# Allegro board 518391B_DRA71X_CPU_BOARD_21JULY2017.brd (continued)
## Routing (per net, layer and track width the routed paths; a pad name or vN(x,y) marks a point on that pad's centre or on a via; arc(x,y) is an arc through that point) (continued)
VIO_3V3_SD: length 12.1
  TOP w0.254: C544.1 v2(149.35,128.27) ; U70.8 155.84,130.19 v2(155.57,129.92) ; C545.1 v2(149.35,130.81) ; C542.1 v2(149.35,133.35) ; U70.7 v2(155.58,130.69)
  TOP w0.305: C541.1 151,130.18 C540.1 149.73,130.43 v2(149.35,130.81)
  BOTTOM w0.254: U68.1 149.34,133.34 v2(149.35,133.35) ; U67.1 149.34,130.8 v2(149.35,130.81) ; U66.1 149.34,128.26 v2(149.35,128.27)
  BOTTOM w0.305: P10.4 149.79,130.37 v2(149.35,130.81)
VMEDIA_16V0: length 14.2
  TOP w0.305: TP62.1 146.3,13.39 ; TP62.1 145.62,12.7 ; TP62.1 146.3,12.01
  BOTTOM w0.305: 145.77,13.24 TP62.1 ; TP62.1 146.84,12.16 ; TP62.1 146.84,13.24 ; TP62.1 145.77,12.16 ; J17.8 125.54,22.12 ; J17.8 123.93,20.51 ; J17.8 125.54,20.51 ; J17.8 123.93,22.12 ; J17.7 123.54,22.12 ; J17.7 121.93,22.12 ; J17.7 121.93,20.51 ; J17.7 123.54,20.51
  vias: v3(143.51,12.19) v3(145.16,13.59)
VOSNS: length 6.2
  TOP w0.305: R47.2 C66.2 57.4,110.87 55.89,112.39 U19.12
VOUT3_INTB: length 76.4
  TOP w0.127: U30.31 140.34,71.37 v2(140.32,71.37) ; v1(95.24,91.53) U27.AC10
  LY3 w0.133: v2(137.41,95.5) 135.51,97.41 131.95,97.41 131.83,97.54 130.43,97.54 129.54,98.42 120.27,98.42 119.25,97.41 107.06,97.41 106.81,97.16 98.68,97.16 97.16,95.63 v2(96.01,95.63)
  LY4 w0.133: v2(137.41,95.5) 138.56,94.36 138.56,91.44 139.95,90.04 139.95,77.09 140.38,76.67 140.38,71.43 v2(140.32,71.37) ; v2(96.01,95.63) 95.24,94.86 v1(95.24,91.53)
  BOTTOM w0.127: R237.2 v2(96.01,95.63)
VOUT3B_CLK: length 41
  TOP w0.127: v2(142.76,61.71) 142.34,62.13 U30.10 ; R73.1 119.85,76.96 120.9,76.96 121.16,77.22 130.43,77.22 131.06,76.58 132.84,76.58 133.48,75.95 136.91,75.95 137.41,75.44 143.64,75.44 v2(144.02,75.06)
  LY4 w0.133: v2(144.02,75.06) 144.65,74.42 144.65,69.47 143.89,68.71 143.89,64.13 142.76,63.01 v2(142.76,61.71)
VOUT3B_D0: length 60.5
  TOP w0.127: 133.99,81.28 135.05,81.28 J8.2 ; U27.F1 101.86,80.16 105.8,76.21 116.19,76.21 116.59,75.82 121.16,75.82 121.67,76.33 127.63,76.33 127.89,76.58 129.16,76.58 129.54,76.2 131.95,76.2 132.08,76.33 132.72,76.33 133.35,75.69 136.4,75.69 v2(137.16,74.93) ; U30.43 136.39,66.05 v2(136.14,66.29)
  LY4 w0.133: v2(136.14,66.29) 136.65,66.8 136.65,72.39 137.16,72.9 v2(137.16,74.93) 137.16,75.44 136.83,75.77 J8.2
  BOTTOM w0.127: J8.2 135.25,79.5 135.22,79.46 R417.2
VOUT3B_D1: length 62.9
  TOP w0.102: U27.E2 100.44,79.18 101.52,79.18
  TOP w0.127: v2(136.53,74.55) 135.89,74.55 135.38,75.06 134.6,75.06 134.47,75.18 128.78,75.18 128.52,75.44 122.43,75.44 122.05,75.06 116.21,75.06 115.81,75.45 105.49,75.45 101.75,79.18 101.52,79.18 ; J8.4 135.76,82.55 133.99,82.55 ; U30.44 135.88,65.54 v2(135.64,65.79)
  LY4 w0.133: v2(135.64,65.79) 135.64,66.55 136.39,67.3 136.39,74.42 v2(136.53,74.55) 136.53,75.44 135.89,76.07 135.89,80.54 J8.4
  BOTTOM w0.127: J8.4 135.33,81.48 135.22,81.37 R418.2
VOUT3B_D2: length 64.2
  TOP w0.127: U27.E1 101.79,79.51 105.59,75.71 115.94,75.71 116.33,75.31 121.79,75.31 122.22,75.74 128.73,75.74 129.03,75.44 135.64,75.44 v2(135.89,75.18) ; U30.45 v2(136.14,65.04) ; 133.99,83.82 135.38,83.82 135.74,83.46 J8.6
  LY4 w0.133: J8.6 135.38,82.02 135.38,75.69 v2(135.89,75.18) 136.08,75 136.08,67.62 135.13,66.67 135.13,65.53 135.62,65.04 v2(136.14,65.04)
  BOTTOM w0.127: J8.6 135.28,83.46 135.22,83.4 R419.2
VOUT3B_D3: length 67.8
  TOP w0.127: J8.8 135.61,85.45 135.25,85.09 133.99,85.09 ; U27.C1 101.65,78.21 105.17,74.69 115.3,74.69 116.59,73.41 122.43,73.41 123.7,74.68 127.76,74.68 128.02,74.42 133.48,74.42 133.99,73.91 135.38,73.91 v2(135.64,74.17) ; U30.46 v2(135.41,64.54)
  LY4 w0.133: J8.8 134.87,83.49 134.87,75.44 135.64,74.68 v2(135.64,74.17) 135.82,73.99 135.82,68 134.87,67.05 134.87,65.09 v2(135.41,64.54)
  BOTTOM w0.127: R413.2 135.22,85.43 135.25,85.47 135.28,85.45 J8.8
VOUT3B_D4: length 69.4
  TOP w0.127: U27.D1 101.72,78.86 105.38,75.2 115.68,75.2 116.08,74.8 122.43,74.8 122.81,75.18 128.27,75.18 128.52,74.93 134.37,74.93 v2(134.87,74.42) ; J8.10 135.76,86.36 133.99,86.36 ; U30.47 v2(136.05,64.04)
  LY4 w0.133: v2(136.05,64.04) 135.31,64.04 134.61,64.75 134.61,67.18 135.56,68.13 135.56,73.49 134.87,74.17 v2(134.87,74.42) 134.49,74.8 134.49,85.09 J8.10
  BOTTOM w0.127: R420.2 135.22,87.46 135.25,87.5 135.33,87.43 J8.10
VOUT3B_D5: length 72.5
  TOP w0.102: U27.D2 100.44,78.53 101.52,78.53
  TOP w0.127: J8.12 135.05,87.63 133.99,87.63 ; U30.48 v2(135.43,63.55) ; 101.52,78.53 101.69,78.53 105.27,74.94 115.56,74.94 115.95,74.55 122.81,74.55 123.19,74.93 128.02,74.93 128.27,74.68 133.86,74.68 v2(134.11,74.42)
  LY4 w0.133: J8.12 134.11,86.69 v2(134.11,74.42) 135.3,73.24 135.3,68.49 134.24,67.44 134.24,64.26 134.96,63.55 v2(135.43,63.55)
  BOTTOM w0.127: R421.2 135.22,89.37 135.25,89.41 J8.12
VOUT3B_D6: length 54.6
  TOP w0.127: v2(111.25,58.42) 111.25,68.45 107.06,72.64 106.17,72.64 105.16,73.66 105.16,73.98 101.58,77.56 U27.B1 ; U30.1 137.84,62.02 137.16,61.34 136.65,61.34 v2(135.51,60.2)
  LY3 w0.133: v2(111.25,58.42) 111.74,57.93 133.24,57.93 v2(135.51,60.2)
  BOTTOM w0.127: v2(135.51,60.2) 135.51,61.09
VOUT3B_D7: length 59.1
  TOP w0.102: U27.B2 100.24,77.56 100.56,77.24 101.52,77.24
  TOP w0.127: v2(110.36,58.42) 110.36,62.61 109.47,63.5 109.47,69.6 106.68,72.39 105.79,72.39 104.78,73.41 104.78,73.99 101.52,77.24 ; U30.2 v2(138.34,61.82)
  LY3 w0.133: v2(110.36,58.42) 110.87,58.93 111.63,58.93 112.37,58.19 131.6,58.19 134.24,60.83 137.35,60.83 v2(138.34,61.82)
  BOTTOM w0.127: v2(138.34,61.82) 137.17,62.99 136.14,62.99 135.51,62.36
VOUT3B_D8: length 44.6
  TOP w0.102: U27.C2 100.44,77.88 101.52,77.88
  TOP w0.127: v2(138.18,72.01) 138.34,71.85 U30.35 ; 101.52,77.88 101.62,77.88 105.23,74.27 v2(105.77,74.27)
  LY3 w0.133: v2(105.77,74.27) 106.17,74.68 115.95,74.68 116.84,73.79 124.71,73.79 125.46,73.04 130.31,73.04 130.61,73.33 133.37,73.33 133.77,73.74 134.79,73.74 135.76,72.77 137.41,72.77 v2(138.18,72.01)
  BOTTOM w0.127: RJ17.2 v2(138.18,72.01)
VOUT3B_D9: length 47.2
  TOP w0.127: U30.36 137.84,71.2 137.67,71.37 137.67,74.3 v2(138.18,74.8) ; U27.D3 v1(99.79,79.18)
  LY3 w0.133: v2(138.18,74.8) 137.54,75.44 136.78,75.44 136.52,75.69 134.62,75.69 133.99,75.06 127.76,75.06 127.04,75.78 117.64,75.78 117.14,76.28 105.58,76.28 103.38,78.49 100.49,78.49 v1(99.79,79.18)
  BOTTOM w0.127: RJ16.2 v2(138.18,74.8)
VOUT3B_D10: length 47
  TOP w0.127: U27.A2 100.11,76.11 104.09,72.14 v2(105.16,72.14) ; U30.37 134.41,69.04 v2(133.73,69.72) 134.87,70.87 v2(134.87,73.02)
  LY3 w0.133: v2(105.16,72.14) 105.54,72.52 112.65,72.52 113.54,71.63 115.32,71.63 116.71,73.02 124.47,73.02 125.09,72.39 131.32,72.39 131.74,72.81 134.66,72.81 v2(134.87,73.02)
  BOTTOM w0.127: v2(133.73,69.72) 133.73,69.47 RJ20.2
VOUT3B_D11: length 46
  TOP w0.102: 99.79,76.17 99.79,77.04 99.46,77.37 U27.B3
  TOP w0.127: 99.79,76.17 99.79,76.08 104.24,71.63 v2(105.79,71.63) ; U30.38 133.82,68.54 v2(133.73,68.45)
  LY3 w0.133: v2(105.79,71.63) 106.3,72.14 112.27,72.14 113.04,71.37 115.56,71.37 116.95,72.76 124.22,72.76 125.35,71.63 v2(131.57,71.63)
  BOTTOM w0.127: v2(131.57,71.63) 131.57,68.83 131.95,68.45 132.72,68.45 RJ21.2 133.73,68.2 v2(133.73,68.45)
VOUT3B_D12: length 48.7
  TOP w0.102: 100.81,76.17 100.44,76.55 100.44,77.04 100.25,77.23 99.96,77.23 99.79,77.4 99.79,77.88 U27.C3
  TOP w0.127: v2(104.66,72.78) 101.52,75.92 101.07,75.92 100.81,76.17 ; U30.39 134.59,68.04 134.49,67.94 133.48,67.94 133.22,68.2 133.22,70.48 v2(133.73,70.99) 133.77,71.03 133.77,72.98 v2(134.09,73.3)
  LY3 w0.133: v2(134.09,73.3) 133.86,73.07 130.86,73.07 130.56,72.78 125.22,72.78 124.59,73.41 116.08,73.41 115.32,72.64 113.28,72.64 112.9,73.02 104.9,73.02 v2(104.66,72.78)
  BOTTOM w0.127: v2(133.73,70.99) 133.73,70.74 RJ19.2
VOUT3B_D13: length 48.1
  TOP w0.127: U30.40 134.09,67.54 v2(133.73,67.18) ; U27.C4 v1(99.14,77.88)
  LY3 w0.133: v2(132.97,73.79) 130.56,73.79 130.07,73.3 125.71,73.3 124.85,74.16 117.1,74.16 116.2,75.06 104.14,75.06 102.23,76.96 100.06,76.96 v1(99.14,77.88)
  LY4 w0.133: v2(132.97,73.79) 133.77,72.98 133.77,71.97 134.37,71.37 134.37,68.2 133.73,67.56 v2(133.73,67.18)
  BOTTOM w0.127: v2(133.73,67.18) 133.73,66.93 RJ22.2
VOUT3B_D14: length 49.8
  TOP w0.127: U30.41 134.35,67.04 133.99,66.67 133.35,66.67 132.84,67.18 132.84,71.88 v2(133.35,72.39) ; U27.A3 99.46,76.04 104.39,71.12 106.3,71.12 v2(106.68,71.5)
  LY3 w0.133: v2(106.68,71.5) 106.93,71.75 111.63,71.75 112.28,71.11 115.8,71.11 117.19,72.5 123.97,72.5 125.35,71.12 132.08,71.12 v2(133.35,72.39)
  BOTTOM w0.127: v2(133.35,72.39) RJ18.2
VOUT3B_D15: length 48.6
  TOP w0.102: 99.14,76.17 99.14,77.23 U27.B4
  TOP w0.127: 99.14,76.17 99.14,76.01 107.19,67.96 v2(107.19,65.41) ; v2(133.73,65.91) 134.61,66.79 136.28,66.79 136.53,66.54 U30.42
  LY3 w0.133: v2(133.73,65.91) 132.08,64.26 128.66,64.26 128.38,63.99 123.22,63.99 122.95,64.26 121.79,64.26 121.41,63.88 119.63,63.88 119.51,63.75 114.68,63.75 113.16,65.28 107.31,65.28 v2(107.19,65.41)
  BOTTOM w0.127: v2(133.73,65.91) 133.73,65.66 RJ23.2
VOUT3B_D16: length 53.1
  TOP w0.127: U30.25 v2(143.34,71.37) ; v2(143.12,76.15) 143.13,76.16 143.13,77.09 142.24,77.98 135.76,77.98 133.6,80.14 118.36,80.14 117.98,79.76 114.43,79.76 113.28,80.9 105.48,80.9 102.32,84.06 U27.M1
  LY4 w0.133: v2(143.12,76.15) 143.51,75.76 143.51,73.41 143.34,73.23 v2(143.34,71.37)
VOUT3B_D17: length 53.2
  TOP w0.102: 101.52,83.72 101.51,83.73 100.44,83.73 U27.M2
  TOP w0.127: U30.26 v2(142.84,70.76) ; v2(142.62,76.83) 141.73,77.72 134.37,77.72 132.21,79.88 118.62,79.88 118.24,79.5 114.17,79.5 113.03,80.64 105.36,80.64 102.29,83.72 101.52,83.72
  LY4 w0.133: v2(142.62,76.83) 142.62,75.82 143.13,75.31 143.13,73.53 142.88,73.28 142.88,70.8 v2(142.84,70.76)
VOUT3B_D18: length 52.1
  TOP w0.102: 101.52,83.09 100.44,83.09 U27.L2
  TOP w0.127: v2(142.15,76.07) 141.73,76.07 140.59,77.22 134.11,77.22 131.95,79.38 119.13,79.38 118.66,78.91 113.22,78.91 112.89,78.57 106.69,78.57 102.18,83.09 101.52,83.09 ; U30.27 v2(142.34,71.37)
  LY4 w0.133: v2(142.15,76.07) 142.15,73.36 142.37,73.15 142.37,71.4 v2(142.34,71.37)
VOUT3B_D19: length 51.1
  TOP w0.127: v2(141.73,76.83) 141.1,77.47 134.24,77.47 132.08,79.63 118.87,79.63 118.49,79.25 113.54,79.25 113.16,79.63 106.02,79.63 102.24,83.41 U27.L1 ; U30.28 v2(141.84,70.76)
  LY4 w0.133: v2(141.73,76.83) 141.73,73.02 141.86,72.9 141.86,70.78 v2(141.84,70.76)
VOUT3B_D20: length 52.5
  TOP w0.127: U30.29 v2(141.34,71.37) ; U27.K3 v1(99.79,82.43)
  LY3 w0.133: v1(99.79,82.43) 100.45,82.43 102.11,80.77 104.65,80.77 106.93,78.49 112.65,78.49 113.54,79.38 118.36,79.38 119.37,78.37 120.77,78.37 122.42,76.71 127.37,76.71 128.14,75.95 131.45,75.95 131.83,76.33 136.52,76.33 137.03,76.83 137.92,76.83 138.43,76.33 138.98,76.33 139.23,76.58 140.46,76.58 v2(140.97,76.07)
  LY4 w0.133: v2(141.34,71.37) 141.34,72.38 141.47,72.51 141.47,75.57 v2(140.97,76.07)
VOUT3B_D21: length 49.6
  TOP w0.102: 101.52,82.43 100.44,82.43 U27.K2
  TOP w0.127: U30.32 v2(139.84,70.76) ; v2(139.95,76.07) 139.66,76.37 138.37,76.37 138.03,76.71 133.86,76.71 131.7,78.87 119.63,78.87 119.16,78.4 113.58,78.4 113.25,78.07 106.48,78.07 102.12,82.43 101.52,82.43
  LY4 w0.133: v2(139.95,76.07) 139.95,75.55 139.96,75.55 139.96,72.14 139.83,72.01 139.83,70.78 v2(139.84,70.76)
VOUT3B_D22: length 48.1
  TOP w0.127: v2(139.19,75.95) 138.43,75.95 137.92,76.45 133.73,76.45 131.57,78.61 119.89,78.61 119.42,78.14 113.68,78.14 113.35,77.81 106.38,77.81 102.08,82.11 U27.J1 ; U30.33 v2(139.34,71.35)
  LY4 w0.133: v2(139.34,71.35) 139.32,71.37 139.32,72.14 139.7,72.52 139.7,75.44 v2(139.19,75.95)
VOUT3B_D23: length 48.1
  TOP w0.127: U30.34 v2(138.84,70.84) ; U27.K1 102.15,82.76 106.59,78.32 112.99,78.32 113.32,78.65 118.91,78.65 119.38,79.12 131.83,79.12 133.99,76.96 138.51,76.96 v2(138.68,76.78)
  LY4 w0.133: v2(138.68,76.78) 138.68,72.9 138.84,72.74 v2(138.84,70.84)
VOUT3B_DE: length 58.4
  TOP w0.102: 101.52,81.79 100.44,81.79 U27.J2
  TOP w0.127: U30.5 v2(139.84,61.21) ; v2(137.67,75.86) 137.33,76.2 133.6,76.2 132.25,77.56 131.1,77.56 130.3,78.36 120.14,78.36 119.51,77.72 118.36,77.72 117.94,77.3 117.39,77.3 116.8,77.89 113.79,77.89 113.46,77.56 106.27,77.56 102.04,81.79 101.52,81.79
  LY4 w0.133: v2(137.67,75.86) 137.67,64.39 139.84,62.22 v2(139.84,61.21)
VOUT3B_HSYNC: length 58
  TOP w0.127: U27.K4 v1(99.14,82.43) ; U30.3 v2(138.84,61.21)
  LY4 w0.133: v2(138.84,61.21) 136.02,61.21 132.97,64.26 132.97,70.99 131.52,72.44 v2(131.52,77.98) ; v2(114.55,80.64) 112.39,80.64 111.89,81.15 102.18,81.15 101.67,81.66 101.64,81.66 100.49,82.82 99.52,82.82 v1(99.14,82.43)
  BOTTOM w0.127: v2(131.52,77.98) 130.81,77.98 129.79,78.99 116.2,78.99 v2(114.55,80.64)
VOUT3B_VSYNC: length 55.3
  TOP w0.127: v2(131.95,77.01) 131.14,77.01 130.05,78.1 120.4,78.1 119.63,77.34 118.36,77.34 118.07,77.05 117.13,77.05 116.55,77.64 113.89,77.64 113.56,77.3 106.17,77.3 105.49,77.98 102.01,81.46 U27.H1 ; U30.4 v2(139.34,61.82)
  LY4 w0.133: v2(131.95,77.01) 131.95,73.66 132.84,72.77 132.84,71.88 133.31,71.42 133.31,64.56 135,62.86 138.3,62.86 v2(139.34,61.82)
VPOC_DISPLAY: length 3
  LY4 w0.635: 159.27,69 P2.2 158.21,67.93
  BOTTOM w0.305: C454.1 v2(164.21,59.56)
  vias: v2(162.31,60.5) v2(163.32,60.5)
VREF_DBG: length 21.4
  TOP w0.203: J14.12 119.68,46.61 120.19,46.1 121.41,46.1 121.92,45.59 123.99,45.59 126.15,47.75 126.15,48.81 126.62,49.28 126.62,51.31 127,51.69 R308.2
  TOP w0.305: R308.2 125.09,54.1 124.71,54.48 123.06,54.48 122.75,54.17 J14.1
VSW_3V3: length 2.7
  TOP w0.305: 66.37,44.96 TP42.1 ; TP42.1 67.06,45.64 ; TP42.1 67.06,44.27 ; TP42.1 67.74,44.96
VSW_5V0: length 292.7
  TOP w0.203: U17.10 114.6,152.83 v2(114.3,152.53)
  TOP w0.279: U32.8 84.47,60.67 v2(84.48,60.68)
  TOP w0.305: R186.2 v2(66.93,16.89) ; R185.2 v2(69.34,16.89) ; TP57.1 95.17,24.64 ; TP57.1 93.8,24.64 ; TP57.1 94.49,25.32 ; TP57.1 94.49,23.95 ; R31.1 R30.2 ; R30.2 v2(110.74,153.54) ; R30.2 R28.2 ; v2(68.58,11.43) 68.33,11.68 R167.1 R166.1
  LY3 w0.305: v2(116.59,118.75) 116.59,111 121.79,105.79 131.57,105.79 136.4,100.97 141.6,100.97 142.24,100.33 150.24,100.33 v2(150.75,99.82) ; v2(94.49,25.78) 106.93,25.78 111.12,29.97 122.17,29.97 123.57,31.37 135.51,31.37 138.94,34.8 138.94,45.08 140.12,46.27 151.47,46.27 151.89,45.85 156.59,45.85 159,48.26 159,54.99 158.24,55.75 158.24,60.45 153.54,65.15 v2(153.54,71.25)
  LY3 w0.508: v2(68.96,47.37) 68.96,45.97 71.25,43.69 71.25,40.13 74.55,36.83 74.55,34.54 75.31,33.78 75.31,32.26 75.82,31.75 v2(75.82,28.32) ; v2(75.44,62.36) 76.2,63.12 82.04,63.12 v2(84.48,60.68)
  LY4 w0.305: 94.49,23.95 TP57.1 ; TP57.1 94.49,25.32 ; TP57.1 95.17,24.64 ; TP57.1 93.8,24.64 ; v2(116.08,148.59) 116.59,148.08 v2(116.59,118.75) ; v2(153.54,71.25) 153.54,81.91 150.75,84.71 150.75,95.38 150.11,96.01 150.11,97.41 150.75,98.04 v2(150.75,99.82)
  BOTTOM w0.203: v2(114.3,152.53) C269.1
  BOTTOM w0.305: v2(116.08,148.59) 114.3,150.37 v2(114.3,152.53) 113.79,152.53 113.41,152.15 112.14,152.15 v2(110.74,153.54) ; C527.1 v2(75.82,28.32) ; v2(84.48,60.68) C441.1
  BOTTOM w0.508: v2(75.44,62.36) 75.44,63.63 74.93,64.13 74.04,64.13 72.26,62.36 71.25,62.36 68.6,59.71 68.6,47.73 v2(68.96,47.37)
  vias: v2(76.96,29.34) v2(93.34,25.78)
VSYS_3V3: length 175.5
  TOP w0.254: 85.97,60.44 v2(85.67,60.73) ; v2(87.35,60.86) 86.97,60.47 U32.3 ; U32.22 80.8,54.38 v2(80.77,54.36) ; v2(83.46,60.73) 83.47,60.73 U32.10
  TOP w0.279: v2(80.48,56.48) 80.68,56.48 80.75,56.41 81.15,56.41 81.21,56.39 81.23,56.38 U32.18 ; U32.5 85.97,60.44 ; v2(90.04,55.77) 89.92,55.89 U32.42 ; U32.37 v2(89.92,53.39) ; U32.46 v2(89.63,57.88)
  TOP w0.305: U24.16 v2(121.78,97.65) ; U42.4 v2(88.7,33.2) ; R22.2 v2(78.74,129.35) ; R23.2 v2(72.26,129.48) ; v2(70.87,16.89) R188.2 R187.2 ; 124.84,29.97 124.21,29.97 v2(123.82,30.35) ; v2(136.91,53.21) 137.23,52.88 U37.34 ; v2(86.36,50.55) 86.36,51.18 85.97,51.57 U32.32 ; U37.60 127.11,44.35 v2(126.85,44.09) ; U45.5 131.83,29.97 v2(131.44,30.35) ; U38.8 v2(108.2,44.7) ; Q8.4 88.38,39.86 v2(88.39,39.88) ; U37.23 v2(141.08,45.35) ; v2(84.2,50.8) 84.47,51.07 U32.29 ; U37.8 v2(133.74,38.99) ; R41.2 v2(70.48,112.52) ; v2(110.11,36.45) C190.1
  TOP w0.508: v2(142.62,41.66) 143.05,41.66 C181.1 143.05,40.64 v2(142.62,40.64) ; 130.75,31.62 124.33,31.62 123.82,31.11 v2(123.82,30.35) ; 130.75,31.62 131.44,30.93 v2(131.44,30.35) ; 130.75,31.62 130.81,31.68 v2(130.81,38.35)
  LY3 w0.305: v2(70.87,16.89) 71.5,17.53 71.5,25.65 70.36,26.8 70.36,33.65 68.71,35.31 68.71,37.21 v2(67.06,38.86)
  LY3 w0.508: v2(79.26,152) 79.26,149.08 v2(80.39,147.95) 80.39,146.65 v2(79.39,145.65) 79.39,144.64 80.9,143.13 80.9,141.99 v2(80.52,141.6) ; v2(101.73,117.35) 101.22,117.35 100.84,116.97 100.84,116.08 101.47,115.44 101.47,115.06 103.12,113.41 111.89,113.41 120.78,104.52 v2(121.79,104.52)
  LY4 w0.508: v2(78.74,129.35) 78.74,130.81 77.98,131.57 77.98,133.1 80.96,136.08 80.96,141.16 v2(80.52,141.6) ; v2(121.78,97.65) 121.79,97.66 v2(121.79,104.52)
  BOTTOM w0.254: v2(84.2,50.8) 84.44,51.04 C475.1 ; C464.1 81.24,55.72 v2(80.48,56.48) ; C447.1 83.24,60.95 v2(83.46,60.73) ; R347.2 106.3,43.69 106.93,44.32 106.99,44.32 107.31,44.65 C497.1 ; v2(80.77,54.36) 80.39,54.36 C470.1 ; R354.1 138.18,41.53 v2(138.05,41.66) ; R319.1 v2(140.46,51.18)
  BOTTOM w0.305: R347.2 R350.1 R351.1 v2(106.3,40) ; C500.2 126.87,44.07 v2(126.85,44.09) ; 88.27,61.47 87.96,61.47 v2(87.35,60.86) ; R345.2 v2(135.89,45.78) ; v2(138.43,43.52) 138.47,43.52 138.68,43.31 R348.1 ; C554.2 78.49,109.63 v2(78.25,109.87) U76.4 ; v2(75.83,126.77) 75.82,126.76 75.82,126.75 75.56,126.49 R217.2 ; v2(121.78,97.65) 121.78,96.91 C290.1 ; R370.2 88.27,40 v2(88.39,39.88) ; C505.2 133.73,39 v2(133.74,38.99) ; R414.2 v2(80.39,147.95) 80.9,148.46 R416.1 ; v2(90.04,55.77) 90.72,55.09 C469.1 ; R376.2 110.11,35.31 v2(110.11,36.45) ; v2(86.36,50.55) 86.36,51.31 86.07,51.6 C474.1 ; C478.2 v2(136.91,53.21) ; C450.1 90.54,58.79 v2(89.63,57.88) ; C548.1 79.12,152.15 v2(79.26,152) U71.5 ; U72.5 v2(79.39,145.65) ; C522.1 v2(123.82,30.35) ; v2(108.2,44.7) C497.1 ; U74.6 v2(28.19,139.06) C549.2 ; R415.2 v2(80.52,141.6) ; C521.1 v2(131.44,30.35)
  BOTTOM w0.508: R374.1 v2(113.54,33.08)
  vias: v2(67.06,40.89) v2(67.06,39.75) v2(68.58,40.39) v2(91.69,37.46) v2(91.69,36.7) v2(93.98,112.9) v2(95,112.9) v2(96.01,112.9) v2(97.03,112.9) v2(98.04,112.9) v2(100.33,118.87) v2(101.09,118.87) v2(102.23,118.87)
VSYS_5V0: length 214.5
  TOP w0.203: U18.16 79.13,127.63 78.87,127.89 v2(78.87,128.4)
  TOP w0.254: U70.4 v2(158.32,132.38) ; U20.4 102.41,115.75 v2(102.23,115.57) ; U48.4 91.36,28.52 v2(91.19,28.7)
  TOP w0.305: 83.64,32.51 TP51.1 ; TP51.1 84.33,33.2 ; TP51.1 85.01,32.51 ; TP51.1 84.33,31.83 ; R143.2 v2(94.11,32)
  TOP w0.508: U46.3 v2(126.11,37.02) ; U45.3 v2(133.73,37.02)
  LY3 w0.305: v2(102.23,115.57) 103.5,114.3 112.27,114.3 121.41,105.16 131.19,105.16 v2(132.21,104.14) 136.02,100.33 v2(141.35,100.33)
  LY4 w0.305: 84.33,31.83 TP51.1 ; TP51.1 84.33,33.2 ; TP51.1 85.01,32.51 ; TP51.1 83.64,32.51 ; v2(102.23,115.57) 102.49,115.82 102.49,117.6 101.98,118.11 99.95,118.11 99.82,118.24 90.68,118.24 84.2,124.71 82.42,124.71 80.26,126.87 79.38,126.87 78.87,127.38 v2(78.87,128.4) ; v2(141.35,100.33) 141.35,93.98 142.24,93.09 142.24,90.3 143.51,89.03 143.51,81.79 145.29,80.01 145.29,76.71 146.69,75.31 146.69,69.85 146.18,69.34 146.18,68.45 146.56,68.07 146.56,61.72 144.78,59.94 144.78,56.77 v2(144.02,56.01)
  LY4 w0.508: v2(158.32,132.38) 146.86,132.38 146.05,131.57 142.37,131.57 132.21,121.41 v2(132.21,104.14)
  BOTTOM w0.305: v2(133.73,37.02) 133.73,37.97 134.62,38.86 134.62,52.96 137.67,56.01 v2(144.02,56.01)
  BOTTOM w0.508: v2(126.11,37.02) 126.11,35.81 ; v2(133.73,37.02) 133.73,35.81
  vias: v2(92.96,29.21) v2(94.49,30.61) v2(94.49,29.84) v2(94.49,28.7)
VSYS_10V5: length 19.7
  TOP w0.305: 151.26,25.6 TP55.1 ; TP55.1 151.94,26.29 ; TP55.1 150.57,26.29 ; TP55.1 151.26,26.98 ; U19.24 v2(51.33,121.39) ; R172.2 150.24,23.49 151.69,24.94 L54.2
  LY4 w0.305: TP55.1 151.26,26.98 ; TP55.1 151.26,25.6 ; TP55.1 151.94,26.29 ; TP55.1 150.57,26.29
  vias: v2(151.26,28.07)
VSYS_16V0: length 40.3
  TOP w0.305: 70.48,129.54 71.37,128.65 71.37,114.55 66.8,109.98 R46.2 60.83,109.98 60.71,110.11 R47.1 ; 65.1,134.24 TP7.1 ; TP7.1 65.79,133.55 ; TP7.1 65.79,134.93 ; TP7.1 66.47,134.24 ; R182.1 v2(161.8,11.68)
  LY5_PWR w0.305: TP7.1 66.47,134.24 ; TP7.1 65.79,134.93 ; TP7.1 65.79,133.55 ; TP7.1 65.1,134.24 ; J13.1 162.69,54.66 ; J13.1 163.75,53.59 ; J13.1 161.62,53.59 ; J13.1 162.69,52.53
  BOTTOM w0.305: C266.2 v2(59.82,132.33)
  vias: v2(60.71,132.33) v2(61.59,132.33) v2(62.48,132.33) v2(63.75,132.33) v2(64.64,132.33) v2(65.53,132.33) v2(66.42,132.33) v2(67.69,132.33) v2(68.58,132.33) v2(69.47,132.33) v2(70.36,132.33) v2(92.33,152.4) v2(94.36,151.13) v2(94.36,150.11) v2(94.36,149.1) v2(142.37,31.62) v2(142.37,30.61) v2(143,29.97) v2(143.38,21.08) v2(144.02,29.97) v2(144.4,21.08) v2(145.16,20.45) v2(145.16,19.43) v2(161.93,18.03) v2(163.07,18.03) v2(164.08,18.03) v2(165.1,18.03)
VTT_DDR:
  vias: v2(48.51,69.98) v2(50.67,69.98) v2(53.47,69.98) v2(56.13,69.98) v2(58.8,69.98) v2(61.59,69.85) v2(61.72,58.93) v2(61.72,57.91) v2(61.72,56.77) v2(61.72,55.75) v2(61.72,54.61) v2(61.72,53.59) v2(62.71,52.32) v2(63.12,69.85) v2(64.26,69.85)
VTUN_1V8: length 18.5
  TOP w0.305: v2(52.7,56.13) C150.1 C149.1 51.69,55.5 50.77,54.58 U34.25 ; TP52.1 64.01,32.94 ; TP52.1 64.69,32.26 ; TP52.1 64.01,31.57 ; TP52.1 63.32,32.26 ; U36.45 32.07,56.07 32.51,56.52 32.89,56.52 33.78,57.4 C138.1 C139.1 v2(34.8,57.47)
  LY3 w0.305: 64.01,31.57 TP52.1 ; TP52.1 64.69,32.26 ; TP52.1 64.01,32.94 ; TP52.1 63.32,32.26
  BOTTOM w0.305: C460.1 52.45,56.39 v2(52.7,56.13) ; v2(34.8,57.47) 34.8,57.78 C452.1
  vias: v2(63.12,33.02)
VTUN_3V3: length 16.1
  TOP w0.254: v2(52.83,46.1) C170.2 C169.2 50.37,46.78 U34.12 ; v2(34.04,41.91) C180.2 C179.2 31.57,42.6 U36.18
  TOP w0.305: TP56.1 64.01,25.45 ; TP56.1 63.32,24.76 ; TP56.1 64.01,24.08 ; TP56.1 64.69,24.76
  TOP w0.508: R162.2 v2(37.85,23.49) ; R153.2 v2(56.52,27.56)
  LY3 w0.305: 64.01,24.08 TP56.1 ; TP56.1 63.32,24.76 ; TP56.1 64.01,25.45 ; TP56.1 64.69,24.76
  BOTTOM w0.254: C501.2 v2(34.04,41.91) ; v2(52.83,46.1) C494.2
  vias: v2(63.12,25.53)
VUSB_5V0: length 23.1
  TOP w0.305: U12.15 v2(156.53,146.81) ; 83.95,149.81 TP2.1 83.26,150.5 ; R7.1 v2(127.25,144.14) ; U12.14 155.89,146.62 v2(155.7,146.81)
  TOP w0.508: v2(159.64,145.54) 159.64,146.05 C12.1 158.62,146.05 v2(158.62,145.54)
  LY3 w0.305: 83.95,149.81 TP2.1 ; TP2.1 83.95,151.18 ; TP2.1 83.26,150.5 ; TP2.1 84.63,150.5
  BOTTOM w0.305: v2(87.5,143.13) 88.99,141.64 90.12,141.64 90.42,141.34 90.42,140.46 91.19,139.7 R210.2 ; R198.1 v2(153.54,149.48) ; C263.1 155.57,146.69 v2(155.7,146.81) ; 92.33,147.83 93.09,148.59 v2(95.76,148.59) ; C262.2 v2(96.52,146.81)
  vias: v2(82.8,148.97) v2(82.8,147.83) v2(82.8,146.81) v2(82.8,145.67) v2(124.33,144.78) v2(124.59,143.51) v2(124.59,142.49)
W_MMC1_CLK: length 12
  TOP w0.127: U21.46 149.84,102.59 v2(149.48,102.23)
  LY4 w0.133: v2(150.06,110.62) 149.73,110.29 149.73,108.84 150.11,108.46 150.11,105.92 149.48,105.28 v2(149.48,102.23)
  BOTTOM w0.127: RU1.13 v2(150.06,110.62)
W_MMC1_CMD: length 15.1
  TOP w0.127: v2(147.7,102.23) 147.7,102.26 147.84,102.4 U21.44
  LY4 w0.133: v2(147.7,102.23) 147.7,104.27 147.57,104.39 147.57,107.7 148.21,108.33 148.21,111.25 148.08,111.38 148.08,114 v2(148.11,114.02)
  BOTTOM w0.127: RU1.10 v2(148.11,114.02)
W_MMC1_D0: length 6.2
  TOP w0.127: v2(146.69,102.36) 146.84,102.51 U21.43
  BOTTOM w0.127: RU2.3 144.1,104.94 v2(146.69,102.36)
W_MMC1_D1: length 8.5
  TOP w0.127: U21.41 144.84,102.29 144.02,101.47 143.13,101.47 v2(142.49,102.11)
  BOTTOM w0.127: RU2.6 142.15,102.45 v2(142.49,102.11)
W_MMC1_D2: length 10.6
  TOP w0.127: v2(144.14,102.36) 143.84,102.67 U21.40
  LY3 w0.133: v2(144.14,102.36) 146.43,104.65 146.81,104.65 147.7,105.54 150.24,105.54 v2(150.71,105.07)
  BOTTOM w0.127: RU1.3 v2(150.71,105.07)
W_MMC1_D3: length 6.7
  TOP w0.127: U21.42 145.84,102.4 v2(145.8,102.36)
  LY3 w0.133: v2(148.76,104.69) 147.83,103.76 147.19,103.76 v2(145.8,102.36)
  BOTTOM w0.127: RU1.6 v2(148.76,104.69)
WL_EN: length 83.3
  TOP w0.127: U21.9 v2(149.84,121.39) ; v2(133.99,93.22) 131.7,93.22 130.18,91.69 127.13,91.69 126.62,91.19 121.03,91.19 119.55,89.7 114.52,89.7 112.65,91.57 105.54,91.57 104.53,90.56 U27.AB1
  LY4 w0.133: v2(133.99,93.22) 133.99,94.74 133.48,95.25 133.48,96.65 133.6,96.77 133.6,120.52 135.77,122.69 147.82,122.69 148.59,121.92 149.35,121.92 149.84,121.44 v2(149.84,121.39)
  BOTTOM w0.127: R223.2 149.84,120.55 v2(149.84,121.39)
WLAN_IRQ: length 73.7
  TOP w0.102: 101.52,89.53 101.23,89.53 101.17,89.58 100.44,89.58 U27.Y2
  TOP w0.127: U21.17 v2(141.84,121.26) ; 101.52,89.53 113.16,89.53 114.43,88.27 117.35,88.27 118.11,89.03 119.89,89.03 121.28,90.42 126.87,90.42 127.38,90.93 130.68,90.93 131.06,91.31 133.44,91.31 v2(133.99,91.86)
  LY4 w0.133: v2(141.84,121.26) 135.99,121.26 134.37,119.63 134.37,108.97 134.87,108.46 134.87,94.11 134.62,93.85 134.62,92.5 v2(133.99,91.86)
XTAL1: length 5.9
  TOP w0.127: U36.6 v2(25.57,44.28)
  BOTTOM w0.127: v2(25.57,44.28) 22.16,44.28 X2.1
XTAL2: length 3
  TOP w0.127: U36.5 25.07,42.72 v2(24.77,42.42)
  BOTTOM w0.127: v2(24.77,42.42) 23.93,41.58 X2.3
N00722: length 18
  BOTTOM w0.127: R417.1 133.73,78.23 132.21,79.76 132.21,80.77 131.16,81.82 J21.8
N00756: length 16.1
  BOTTOM w0.127: J21.9 131.66,93.43 131.44,93.22 131.44,82.17 133.22,80.39 R418.1
N00790: length 14.2
  BOTTOM w0.127: R419.1 132.97,82.42 131.7,83.69 131.7,92.96 132.16,93.43 J21.10
N00824: length 12.5
  BOTTOM w0.127: J21.11 132.66,93.53 132.84,93.35 132.84,90.8 131.95,89.92 131.95,85.22 132.72,84.45 R413.1
N00858: length 10.3
  BOTTOM w0.127: J21.12 133.16,90.49 132.21,89.53 132.21,86.99 132.72,86.49 R420.1
N00866: length 7.4
  BOTTOM w0.127: J21.13 133.66,93.53 133.48,93.34 133.48,90.3 132.97,89.79 132.97,89.03 133.48,88.52 R421.1
N00972: length 2.1
  BOTTOM w0.127: R424.1 143.16,92.33 J21.32
N01913: length 24.8
  LY4 w0.133: v2(95.33,157.56) 94.61,156.84 80.9,156.84 77.96,153.91 v2(77.96,152)
  BOTTOM w0.127: J20.1 94.73,156.33 U73.4 v2(95.33,157.56) ; U71.4 v2(77.96,152)
N01957: length 13.7
  LY4 w0.133: v2(80.1,139.15) 79.76,139.5 79.76,142.37 80.11,142.72 v2(80.11,142.77) 80.14,142.8 80.14,146.3 79.76,146.69 79.76,148.84 80.11,149.2 v2(80.11,149.25)
  BOTTOM w0.127: U72.1 v2(80.11,142.77) ; Q11.6 v2(80.1,139.15) ; U71.1 v2(80.11,149.25) 80.18,149.19 R416.2
N02093: length 15.6
  TOP w0.254: C139.2 C140.2 C141.2 36.83,59.56 v2(36.32,60.07) ; C139.2 34.8,59.56 v2(34.29,60.07) ; C139.2 C138.2 33.02,59.31 ; 33.02,59.31 C137.2 ; 33.02,59.31 33.02,57.42 32.59,56.98 32.22,56.98 31.57,56.33 U36.46 ; v2(31.88,60.07) 32.38,59.56 C137.2 ; C137.2 C136.2
  BOTTOM w0.254: C452.2 v2(34.29,60.07) ; C451.2 v2(36.32,60.07) ; C453.2 v2(31.88,60.07)
N02103: length 32.1
  LY4 w0.133: v2(78.09,145.53) 78.09,146.19 76.92,147.36 76.92,154.39 80.09,157.56 v2(93.01,157.56)
  BOTTOM w0.127: v2(93.01,157.56) U73.5 93.73,156.98 93.47,156.72 92.58,156.72 J20.2 ; U72.4 v2(78.09,145.53)
N04059: length 10.3
  TOP w0.127: U36.55 27.07,56.75 26.03,57.78 19.81,57.78 J12.1
N04077: length 11.3
  TOP w0.127: U36.54 27.57,56.89 26.29,58.17 20.45,58.17 J12.3
N04157: length 8.9
  TOP w0.127: U36.58 v2(25.57,56.17)
  BOTTOM w0.127: U56.5 23.73,61.86 25.91,59.69 25.91,56.51 v2(25.57,56.17)
N04169: length 6
  TOP w0.127: v2(24.07,56.2) U36.61
  BOTTOM w0.127: U56.2 23.53,59.91 23.75,59.69 23.75,56.52 v2(24.07,56.2)
N04588: length 2
  BOTTOM w0.127: FB1.2 FB2.1
N04640: length 3.4
  TOP w0.127: U36.4 v2(24.57,44.96)
  BOTTOM w0.127: FB2.2 v2(24.57,44.96)
N06498: length 2.3
  TOP w0.127: U36.80 21.16,46.28 v2(21.08,46.35)
  BOTTOM w0.127: v2(21.08,46.35) 21.21,46.23 R333.2
N09601: length 5.5
  TOP w0.254: v2(33.97,40.89) 32.26,40.89 31.07,42.09 U36.17
  BOTTOM w0.254: v2(33.97,40.89) 33.15,40.89
N10369: length 2.3
  TOP w0.127: C178.2 29.59,41.91 29.07,42.43 U36.13
N10535: length 3.8
  TOP w0.254: C186.2 24,40.64 26.07,42.7 U36.7
N13716: length 6.5
  TOP w0.127: U34.35 45.37,55.21 44.32,56.26 43.08,56.26 42.15,57.15 J11.1
N13723: length 8.1
  TOP w0.127: U34.34 45.87,55.22 44.45,56.64 43.31,56.64 J11.3
N14506: length 14.5
  TOP w0.254: v2(54.74,58.8) 54.86,58.67 C152.2 C151.2 C150.2 ; C148.2 50.42,58.55 v2(50.16,58.8) ; C148.2 C147.2 ; C148.2 51.05,58.04 ; C150.2 52.7,58.55 v2(52.45,58.8) ; C150.2 C149.2 51.05,58.04 ; U34.26 49.88,55.34 50.04,55.5 50.55,55.5 51.05,56.01 51.05,58.04
  BOTTOM w0.254: C461.2 v2(50.16,58.8) ; C459.2 v2(54.74,58.8) ; C460.2 v2(52.45,58.8)
N19536: length 5.5
  TOP w0.254: v2(52.77,45.08) C170.1 C169.1 49.86,46.28 49.86,47.52 U34.11
  BOTTOM w0.254: v2(52.77,45.08) C494.1
N22082: length 3.7
  TOP w0.254: C215.1 24.26,33.06 24.13,33.19 L37.2 C196.2
N22086: length 7.1
  TOP w0.254: U36.8 26.57,41.17 24.13,38.73 L29.2 C196.1
N22133: length 2.4
  TOP w0.254: C223.1 C215.2 L45.2
N22186: length 22.4
  TOP w0.254: L53.1 C251.1 ; D17.1 25.53,22.99 24.26,24.26 C223.2 ; L47.1 34.29,28.19 C230.2 R155.1 R156.1 32.38,25.4 30.43,23.44 D18.1
  TOP w0.508: D17.1 C251.1 28.45,22.99 D18.1
N26490: length 12.4
  TOP w0.254: R139.2 C211.2 C221.1 ; D13.1 38.78,31.24 38.52,31.5 C221.1 ; 36.07,31.5 L47.2 36.07,28.32 C230.1 ; 36.07,31.5 C221.1 ; 36.07,31.5 35.69,31.5 35.05,32.13 L41.1
N26569: length 7.6
  TOP w0.254: R139.1 C211.1 37.34,34.67 L41.2 C198.2 R136.2
N26753: length 1.4
  TOP w0.254: L50.2 37.97,30.48
N40192: length 2.4
  BOTTOM w0.127: C483.1 R324.2 R325.1
N40651: length 2
  TOP w0.127: U34.48 43.13,48.31 v2(43.05,48.39)
  BOTTOM w0.127: v2(43.05,48.39) R324.1
N49875: length 10.5
  TOP w0.254: U36.12 28.57,41.54 30.23,39.88 31.62,39.88 33.53,37.97 R136.1 C198.1
N62214: length 9.8
  TOP w0.127: U36.51 29.07,56.88 29.34,57.15 29.34,60.58 30.48,61.72 v2(30.48,62.51)
  BOTTOM w0.127: v2(30.48,62.51) 28.57,62.51
N62220: length 7.6
  TOP w0.127: v2(30.61,60.56) 30.61,59.82 30.07,59.28 U36.49
  BOTTOM w0.127: 28.57,60.56 v2(30.61,60.56)
N62232: length 11
  TOP w0.127: U34.30 47.87,56.39 v2(46.86,57.4)
  BOTTOM w0.127: v2(46.86,57.4) 45.59,58.67 45.59,61.47 44.83,62.23 44.2,62.23 43.93,62.5 U55.5
N62244: length 8.6
  TOP w0.127: U34.28 48.87,56.54 48.51,56.9 v2(48.51,57.4)
  BOTTOM w0.127: v2(48.51,57.4) 48.41,57.51 48.03,57.51 47.5,58.04 47.5,60.83 47.86,61.2 48.89,61.2
N62516: length 8.5
  TOP w0.127: U34.31 47.38,56.13 v2(46.1,57.4)
  BOTTOM w0.127: U55.2 43.97,60.55 44.7,59.82 44.7,58.8 v2(46.1,57.4)
N62529: length 10.6
  TOP w0.127: U34.29 48.37,56.53 v2(47.88,57.02)
  BOTTOM w0.127: 48.89,63.15 47.78,63.15 46.99,62.36 46.99,57.91 v2(47.88,57.02)
N65146: length 1.4
  TOP w0.254: C213.1 21.72,32.77 L45.1
N65896: length 1.4
  TOP w0.254: L37.1 C195.1
N69340: length 1.9
  TOP w0.254: L48.1 C224.1
N69344: length 1.9
  TOP w0.254: L46.1 C219.1
N70553: length 6.2
  TOP w0.254: C197.1 27.43,38.48 L30.2 C187.1 27.56,43.32 U36.10
N70759: length 1.5
  TOP w0.254: L39.2 C197.2
N70763: length 5.1
  TOP w0.254: C229.1 L48.2 L46.2 L39.1
N71180: length 1.4
  TOP w0.254: L53.2 C229.2
N74538: length 6.1
  TOP w0.508: C251.2 J18.1
N75523: length 12.5
  TOP w0.508: D18.2 v2(30.18,21.51) 30.73,20.95 C254.1 ; R162.1 C252.1 v2(33.66,22.48) R156.2
  BOTTOM w0.508: v2(30.18,21.51) 32.69,21.51 v2(33.66,22.48)
N16778201: length 10.5
  BOTTOM w0.127: P10.9 151.82,123.9 149.99,125.73 149.99,125.98 149.73,126.24 147.7,126.24 147.19,125.72 U69.5 144.91,125.72 144.91,125.73
N16778260: length 2.7
  TOP w0.127: R409.1 v2(160.02,124.21)
  BOTTOM w0.127: P10.10 160.32,123.9 v2(160.02,124.21)
N16778400: length 2
  TOP w0.254: C543.1 v2(149.46,125.73)
  BOTTOM w0.254: v2(149.46,125.73) 149.46,125.72 U69.1
N16778910: length 1.9
  TOP w0.254: U70.6 156.1,131.19 155.97,131.32 C547.1
N16783560: length 30.8
  TOP w0.127: R422.2 v2(69.98,110.49)
  LY3 w0.133: v2(78.22,136.26) 78.23,136.24 78.23,133.99 71.25,127 71.25,111.76 v2(69.98,110.49)
  BOTTOM w0.127: Q11.3 v2(78.22,136.26)
N22073312: length 1.6
  TOP w0.127: U31.P6 v2(125.21,60.41)
  BOTTOM w0.127: v2(125.21,60.41) 125.22,60.39 R299.2
N22234321: length 14.2
  TOP w0.127: U27.G21 v1(87.44,80.48)
  LY4 w0.133: v2(78.87,73.88) 80.22,73.88 81.71,75.38 84.08,75.38 84.38,75.68 84.57,75.68 85.07,75.68 85.6,76.21 85.6,78.58 86.14,79.12 86.74,79.12 87.44,79.82 v1(87.44,80.48)
  BOTTOM w0.127: v2(78.87,73.88) 78.84,73.91 R266.2
N22234323: length 11.7
  TOP w0.127: v1(86.79,79.83) U27.F23
  LY4 w0.133: v1(86.79,79.83) 86.46,79.5 86.19,79.5 85.09,78.4 85.09,77.47 83.26,75.64 81.61,75.64 80.77,74.8 v2(79.12,74.8)
  BOTTOM w0.127: R265.2 v2(79.12,74.8)
N22235146: length 14.6
  TOP w0.127: R103.2 v2(96.52,67.56) ; U27.C16 v1(91.34,77.88)
  LY3 w0.133: v1(91.34,77.88) 91.34,77.2 93.11,75.43 93.11,69.86 93.21,69.75 93.21,69.74 93.22,69.74 93.22,69.72 94.36,68.58 96.01,68.58 96.52,68.07 v2(96.52,67.56)
N26762656: length 2.2
  TOP w0.127: v2(113.54,155.83) 113.83,155.54 U17.4
  BOTTOM w0.127: v2(113.54,155.83) 113.79,155.57 R216.2
N26762977: length 2
  TOP w0.127: R33.2 115.32,151.64 115.37,151.69 U17.11
N26765506: length 5.2
  TOP w0.127: v2(123.57,28.57) 123.57,27.81 R151.2
  BOTTOM w0.127: v2(123.57,28.57) 123.06,28.07 R389.1 122.56,27.56 C526.1
N27139839: length 14.5
  TOP w0.127: U27.J20 v1(88.09,82.43)
  LY4 w0.133: v2(78.24,76.31) 78.74,76.81 78.74,78.23 79.63,79.12 82.93,79.12 85.6,81.79 87.44,81.79 v1(88.09,82.43)
  BOTTOM w0.127: v2(78.24,76.31) 78.23,76.33 R264.1
N27139840: length 12.7
  TOP w0.127: U27.K25 84.74,82.76 84.52,82.54 82.69,82.54 81.17,81.03 78.89,81.03 76.77,78.91 76.64,78.91 75.2,77.47 R70.1
N27143875: length 13.3
  TOP w0.127: U27.J25 84.73,82.11 84.65,82.04 82.91,82.04 81.4,80.52 79.12,80.52 77.47,78.86 77.47,78.36 76.33,77.22 75.69,77.22 74.93,76.45 R72.1
N27143876: length 16.8
  TOP w0.102: U27.J24 85.49,81.79 85.49,81.78 84.4,81.78
  TOP w0.127: R74.1 72.77,75.69 73.13,76.05 74.96,76.05 75.1,75.91 75.91,75.91 76.2,76.2 76.2,76.68 77.72,78.21 77.72,78.76 79.23,80.26 81.5,80.26 83.02,81.78 84.4,81.78
N27143878: length 13.8
  TOP w0.127: R75.1 76.05,75.56 76.05,75.57 76.07,75.57 76.45,75.95 76.45,76.58 77.98,78.1 77.98,78.65 79.33,80.01 82.7,80.01 84.15,81.46 U27.H25
N27144522: length 15.2
  TOP w0.102: 101.52,87.63 99.79,87.63 U27.U3
  TOP w0.127: R66.2 111.76,86.49 110.24,88 101.97,88 101.6,87.63 101.52,87.63
N27225962: length 17
  TOP w0.127: U27.E14 92.31,79.51 v1(91.99,79.18)
  LY3 w0.133: v2(98.93,68.33) 98.04,69.21 94.49,69.21 93.63,70.07 93.63,75.92 92.46,77.1 92.46,78.72 v1(91.99,79.18)
  BOTTOM w0.127: R292.1 v2(98.93,68.33)
N27305837: length 11.9
  TOP w0.102: 91.63,76.17 91.63,76.27 91.34,76.55 91.34,77.23 U27.B16
  TOP w0.127: 91.63,76.17 91.63,75.37 90.46,74.2 90.46,73.35 91.57,72.24 91.57,70.99 92.33,70.23 92.33,68.07 92.62,67.78 R100.2
N27305901: length 16
  TOP w0.127: R102.2 v2(95.63,67.56) ; U27.E16 v1(91.34,79.18)
  LY3 w0.133: v1(91.34,79.18) 90.68,78.52 90.68,76.84 92.58,74.94 92.58,69.09 93.85,67.82 95.38,67.82 v2(95.63,67.56)
N27306016: length 8.1
  TOP w0.127: U27.A22 87.11,75.41 85.98,74.27 85.98,74.27 85.91,74.2 85.91,69.92 85.98,69.85 R98.2
N27380264: length 4.4
  TOP w0.127: J14.15 118.68,54.18 118.68,56.07 v2(119.13,56.52)
  BOTTOM w0.127: R309.2 119.4,54.99 119.63,55.23 119.63,56.01 v2(119.13,56.52)
N27473363: length 2.5
  TOP w0.127: R25.2 112.31,156.25 113.75,156.25 114.06,155.94 U17.3
N29751222: length 1.7
  TOP w0.254: v4(13.33,103.76) 13.46,103.63 C81.1
  BOTTOM w0.254: U52.16 14.22,103.76 v4(13.33,103.76)
N29751238: length 1
  BOTTOM w0.254: U52.19 v2(16.01,105.54)
N29751250: length 3.7
  TOP w0.305: R51.2 v4(12.83,108.97)
  BOTTOM w0.305: v4(12.83,108.97) 10.92,107.06 v4(10.67,107.06)
N29751338: length 5.1
  TOP w0.14: v4(15.11,106.43) R52.1 C72.1 R51.1
  BOTTOM w0.14: v4(15.11,106.43) 15.51,106.03 U52.18
N29751389: length 1.7
  TOP w0.14: v4(13.35,101.23) 14.09,101.23 R55.2
  BOTTOM w0.14: U52.11 v4(13.35,101.23)
N29751493: length 1.9
  BOTTOM w0.14: R232.2 20.69,101.22 20.68,101.23 U52.30
N29756671: length 4.8
  TOP w0.305: D16.2 112.27,24.83 C242.1 U47.7
N29756747: length 2.4
  TOP w0.305: D16.1 109.47,26.03 R154.1
N29757886: length 4.8
  TOP w0.127: R152.1 130.68,27.56 v2(131.57,28.45)
  BOTTOM w0.127: R388.2 131.95,28.07 v2(131.57,28.45) 130.68,27.56 C525.1
N29757942: length 3.4
  TOP w0.127: U45.8 v2(136.27,28.45) RJ31.2
  BOTTOM w0.127: R382.1 v2(136.27,28.45)
N29776322: length 5.6
  TOP w0.305: R138.2 160.53,33.4 162.31,31.62 L40.2
N29776336: length 5.6
  TOP w0.305: R138.1 160.53,34.42 162.31,36.19 L40.1
N29776342: length 1.4
  BOTTOM w0.508: v2(164.59,40.77) 165.1,40.26 L62.2
N29776461: length 2.5
  TOP w0.127: C162.1 157.72,51.32 U33.41
N29776463: length 9.7
  TOP w0.127: C162.2 159.26,49.67 arc(159.42,48.84) 159.89,48.13 arc(161.02,47.38) 162.35,47.12 P5.1
  BOTTOM w0.508: L60.1 P5.1
N29776467: length 2.4
  TOP w0.127: U33.42 157.99,51.82 C159.1
N29776493: length 1.3
  TOP w0.127: C159.2 R114.1
N29818953: length 3.2
  TOP w0.127: U37.22 v2(141.58,44.85)
  BOTTOM w0.127: v2(141.58,44.85) 140.23,44.85 C496.1
N29819003: length 1.8
  TOP w0.127: U37.49 v2(128.24,50.55)
  BOTTOM w0.127: C482.2 127.76,50.06 v2(128.24,50.55)
N29842389: length 6.5
  TOP w0.305: U33.7 152.15,56.55 v2(151.93,56.77) ; C133.1 L63.2 v2(150.62,57.4) ; U33.29 v2(151.65,47.51)
  BOTTOM w0.305: C488.1 151.65,48.15 v2(151.65,47.51) ; C466.1 152.15,56.55 v2(151.93,56.77)
N29842691: length 14.5
  TOP w0.112: FL9.2 150.98,67.21 151.21,66.98 153.68,66.98 arc(154.28,67.1) 154.79,67.44 arc(155.28,68.17) 155.45,69.03 155.45,69.26 arc(155.58,69.92) 155.96,70.48 arc(156.66,70.95) 157.49,71.12 157.61,71.12 arc(158.43,70.96) 159.12,70.49 159.38,70.23 P2.1
N29842700: length 14.5
  TOP w0.112: FL9.3 150.98,66.4 151.21,66.62 153.68,66.62 arc(153.7,66.62) 153.71,66.62 153.76,66.62 arc(154.19,66.54) 154.56,66.29 arc(154.93,65.73) 155.07,65.07 155.07,64.43 arc(155.24,63.57) 155.73,62.84 155.96,62.61 arc(156.38,62.33) 156.88,62.23 157.52,62.23 arc(158.19,62.36) 158.75,62.74 arc(159.14,63.32) 159.27,64 P2.3
N29844838: length 2.8
  TOP w0.406: U28.54 22.36,77.41 v2(22.05,77.09)
  BOTTOM w0.406: v2(22.05,77.09) 21.92,76.96 C400.2
N29844877: length 2.8
  TOP w0.406: U28.50 22.31,79.95 v2(22,80.26)
  BOTTOM w0.406: C376.2 21.92,80.34 v2(22,80.26)
N29844974: length 3
  TOP w0.406: U28.48 21.35,81.22 C107.2
N29845018: length 2.7
  TOP w0.406: C97.2 21.72,84.2 22.16,83.76 U28.44
N29845137: length 2.9
  TOP w0.406: v2(22.02,85.29) 22.39,85.66 U28.41
  BOTTOM w0.406: v2(22.02,85.29) 21.92,85.19 C371.2
N29845191: length 2.8
  TOP w0.406: v2(22.05,88.47) 22.31,88.2 U28.37
  BOTTOM w0.406: C330.2 v2(22.05,88.47)
N29845296: length 3
  TOP w0.406: U28.35 21.35,89.47 C93.2
N29845351: length 2.8
  TOP w0.406: U28.31 21.73,92.01 C87.2
N29845492: length 5.8
  TOP w0.203: U28.22 35.12,89.47 35.81,90.17 37.59,90.17 37.85,89.92 RJ7.2
N29845506: length 6
  TOP w0.203: U28.23 34.48,90.11 35.81,91.44 37.59,91.44 37.85,91.19 RJ6.2
N29845705: length 1.7
  TOP w0.127: D11.1 v2(44.32,104.39)
  BOTTOM w0.127: R242.1 v2(44.32,104.39)
N29845767: length 1.7
  TOP w0.127: D10.1 v2(44.32,106.43)
  BOTTOM w0.127: v2(44.32,106.43) R239.1
N29847308: length 3.7
  TOP w0.127: U33.35 v2(154.65,46.86)
  BOTTOM w0.127: v2(154.65,46.86) 154.69,46.83 R339.2 R340.1
N29847310: length 4.5
  TOP w0.127: v2(155.83,46.86) 155.93,46.96 U33.37
  BOTTOM w0.127: v2(155.83,46.86) R338.2 R337.1
N29886815: length 7
  TOP w0.203: C121.1 36.96,75.82 36.96,77.22 35.69,78.49 34.29,78.49 34.1,78.68 U28.5
N29886820: length 5.5
  TOP w0.203: C115.2 37.47,77.34 35.94,78.87 34.67,78.87 34.23,79.31 U28.6
N29886879: length 9.1
  TOP w0.203: R78.1 C112.1 39.5,78.74 37.21,78.74 36.07,79.88 34.92,79.88 34.23,80.58 U28.8
N29886909: length 2.5
  TOP w0.203: C113.2 39.12,77.09 39.37,77.34 C112.2 R80.2
N29887154: length 2.8
  TOP w0.203: C115.1 R82.2 39.75,75.18 R80.1
N29887202: length 8.5
  TOP w0.203: 38.73,74.17 37.59,74.17 36.45,75.31 36.45,77.09 35.5,78.04 U28.4
N29904430: length 5.8
  TOP w0.203: RJ10.2 37.85,87.38 37.59,87.63 35.81,87.63 35.12,86.93 U28.18
N29907236: length 6.3
  TOP w0.203: U28.19 34.86,87.57 35.43,88.14 35.43,88.52 35.81,88.9 37.64,88.9 37.85,88.7 RJ8.2
N29907619: length 6.6
  TOP w0.203: U28.7 34.23,79.95 34.8,79.38 36.07,79.38 37.34,78.1 C113.1
N29927099: length 4
  TOP w0.127: X1.1 v2(143.76,43.69) 143.26,44.2 143,44.2 R130.1
  BOTTOM w0.127: C499.1 144.52,43.69 v2(143.76,43.69)
N29928016: length 2
  TOP w0.127: v2(99.82,45.59) 100.16,45.25 U38.1
  BOTTOM w0.127: v2(99.82,45.59) 99.57,45.34 R343.2
N29951925: length 7.3
  TOP w0.127: v2(131.44,33.97) 131.89,33.53 135.38,33.53 136.27,34.42 U45.1
  BOTTOM w0.127: v2(131.44,33.97) 131.44,34.8
N29951934: length 2.6
  TOP w0.127: U45.4 131.95,35.56 131.44,36.07 v2(131.44,36.7)
  BOTTOM w0.127: v2(131.44,36.7) 131.44,35.94
N30013202: length 17
  TOP w0.102: U27.H24 85.49,81.13 84.4,81.13
  TOP w0.127: R79.1 72.9,74.55 73.51,75.16 75.16,75.16 75.22,75.22 76.13,75.22 76.71,75.8 76.71,76.47 78.23,78 78.23,78.55 79.44,79.76 82.8,79.76 84.18,81.13 84.4,81.13
N30028770: length 15.4
  TOP w0.127: RJ4.3 162.05,101.83 arc(162.31,101.22) 162.92,100.97 168.12,100.97 arc(168.62,100.87) 169.04,100.58 arc(169.41,100.02) 169.55,99.36 169.55,96.93 arc(169.45,96.43) 169.16,96.01 arc(168.8,95.77) 168.38,95.69 U25.11
N30028774: length 2.3
  TOP w0.127: U25.14 153.11,95.69 TP21.1
N30028852: length 3.3
  TOP w0.127: TP29.1 167.04,80.05 U25.1
N30028946: length 7
  TOP w0.127: L11.2 C79.2 165.23,105.79 165.48,106.04 J6.1
N30028952: length 2.2
  TOP w0.127: RJ4.2 L10.2 C79.1
N30028958: length 3.9
  TOP w0.127: RJ4.1 160.91,104.65 160.3,105.26 U21.55
N30029070: length 2.6
  TOP w0.127: U21.48 151.84,100.91 TP19.1
N30029300: length 3.8
  TOP w0.127: Y1.3 134.65,112.17 134.67,112.14 135.51,112.14 135.63,112.26 U21.27
N30029334: length 4.4
  TOP w0.127: TP11.1 133.9,114.26 U21.25
N30029342: length 3.5
  TOP w0.127: DPX1.6 161.04,116.19 arc(160.55,116.1) 160.15,115.82 arc(159.52,115.41) 158.79,115.26 U21.65
N30029362: length 7.3
  TOP w0.127: ANT1.1 174.14,116.84 L8.2 C61.2
N30029368: length 2.9
  TOP w0.127: C61.1 L7.2 DPX1.2
N30029382: length 3.5
  TOP w0.127: U21.68 159.23,118.26 arc(159.59,118.19) 159.89,117.99 160.15,117.73 arc(160.41,117.55) 160.73,117.49 DPX1.4
N30029436: length 3.1
  TOP w0.127: U21.13 145.84,123.15 TP8.1
N30070759: length 5.4
  TOP w0.305: Q1.3 150.26,151.4 149.99,151.13 149.99,148.72 v2(150.11,148.59) U14.2
  BOTTOM w0.305: R200.2 149.73,148.21 v2(150.11,148.59)
N30070805: length 5.9
  TOP w0.305: Q1.5 148.34,150.75 147.7,151.38 D1.1 148.41,153.24 148.46,153.29 v2(148.53,153.29)
  BOTTOM w0.305: R197.1 v2(148.53,153.29) R196.2
N30074897: length 2.3
  TOP w0.127: U12.16 157.16,144.08 v2(157.23,144.02)
  BOTTOM w0.127: v2(157.23,144.02) R205.1
N30074992: length 4.4
  TOP w0.305: TP4.1 152.53,143.13 v2(153.42,144.02) 153.35,144.08 U12.10
  BOTTOM w0.305: v2(153.42,144.02) 153.54,144.14 R206.2
N30075038: length 13.5
  TOP w0.127: v2(160.91,145.41) 161.15,145.18 Q2.6 ; U12.7 v2(153.35,152.15)
  LY4 w0.133: v2(160.91,145.41) 157.35,148.97 156.53,148.97 v2(153.35,152.15)
  BOTTOM w0.127: v2(153.35,152.15) 153.54,151.96 153.54,151.38
N30075044: length 2.4
  TOP w0.127: v2(152.53,152.21) 152.53,152.15 152.59,152.15 152.72,152.02 U12.8
  BOTTOM w0.127: v2(152.53,152.21) 152.53,151.38
N30079884: length 4.7
  TOP w0.305: Q1.6 147.81,150.1 147.07,149.35 v2(147.07,148.59) U13.2
  BOTTOM w0.305: R201.2 146.69,148.21 v2(147.07,148.59)
N30079928: length 6
  TOP w0.305: Q1.2 151.51,150.75 151.89,151.13 151.89,151.89 151.51,152.27 v2(151.51,153.29) 151.46,153.24 D2.1
  BOTTOM w0.305: R195.1 v2(151.51,153.29) R194.2
N30095792: length 2.8
  TOP w0.127: U40.2 116.86,41.89 v2(115.95,42.8)
  BOTTOM w0.127: R346.2 v2(115.95,42.8)
N30095794: length 2.8
  TOP w0.127: TP49.1 121.39,36.34 U40.16
N30098069: length 3.1
  TOP w0.127: U26.7 v2(149.09,82.94) 149.59,83.43 U26.8
  BOTTOM w0.127: R249.2 148.84,83.19 v2(149.09,82.94)
N30100305: length 2.6
  TOP w0.127: U33.8 151.65,56.25 151.51,56.39 151.51,57.15 v2(151.38,57.28)
  BOTTOM w0.127: v2(151.38,57.28) R305.2
N30121035: length 2
  BOTTOM w0.127: R377.2 103.25,34.54 J15.3
N30121052: length 2
  BOTTOM w0.127: R391.2 103.25,26.92 J15.9
N30127007: length 10.2
  TOP w0.102: U27.C24 85.49,77.88 84.74,77.88 84.4,77.55
  TOP w0.127: R81.1 80.06,72.05 81.11,72.05 83.27,74.2 83.27,76.9 83.51,77.14 84,77.14 84.4,77.55
N30127010: length 13.9
  TOP w0.127: U27.G25 84.24,80.81 82.93,79.5 79.54,79.5 78.49,78.44 78.49,77.89 76.96,76.37 76.96,75.69 76.24,74.97 75.82,74.97 75.78,74.93 75.56,74.93 75.31,74.68 R77.1
N30127037: length 11
  TOP w0.102: U27.C23 86.14,77.88 86.14,77.4 85.97,77.23 85.68,77.23 85.49,77.04 85.49,76.78 85.56,76.7 85.56,76.2 85.56,76.2 85.56,76.17
  TOP w0.127: R97.2 81.41,70.61 81.67,70.87 81.67,71.52 82.66,72.52 83.82,72.52 84.29,72.99 84.29,74.47 85.56,75.74 85.56,76.17
N30157685: length 2.1
  BOTTOM w0.508: L61.1 165.1,42.16 L60.2
N30157690: length 1.9
  BOTTOM w0.508: L62.1 L61.2
N30189410: length 12.1
  LY3 w0.133: v2(85.72,165.74) 86.74,164.72 86.74,163.58 v2(87.5,162.81) 88.39,161.93 J3.8
  BOTTOM w0.127: 90.8,162.81 v2(87.5,162.81) ; v2(85.72,165.74) 85.85,165.61 U1.7
N30229067: length 2.1
  TOP w0.127: v2(153.92,56.64) 153.65,56.37 U33.4
  BOTTOM w0.127: v2(153.92,56.64) 153.54,57.02 R306.2
N30256264: length 3.7
  TOP w0.102: 56.15,92.2 U23.L8
  TOP w0.127: R64.1 56.15,89.04 56.15,92.2
N30256273: length 3.7
  TOP w0.102: 56.15,77.97 U29.L8
  TOP w0.127: R76.1 56.15,74.82 56.15,77.97
N30257754: length 4.7
  TOP w0.305: C160.2 R118.2 R117.1 65.15,51.94 64.34,51.13 U35.1
N30258027: length 1.9
  TOP w0.14: R128.1 62.23,47.5 62.36,47.63 U35.7
N30258029: length 1.9
  TOP w0.254: 63.37,47.5 U35.9
  TOP w0.305: 63.37,47.5 63.5,47.36 R129.1
N30258277: length 2.9
  TOP w0.305: C161.2 60.07,50.93 R120.1 61.21,51.18 61.26,51.13 U35.5
N30258482: length 2.8
  TOP w0.508: v2(60.33,69.98) 60.71,70.36 R94.1
  BOTTOM w0.508: R278.1 60.07,70.23 v2(60.33,69.98) 60.07,69.72 C416.1
N30260935: length 16.5
  TOP w0.127: R107.1 v2(79.76,59.18)
  TOP w0.305: v2(91.03,57.02) 90.89,56.88 U32.44
  LY3 w0.133: v2(79.76,59.18) 80.2,58.74 87.69,58.74 89.41,57.02 v2(91.03,57.02)
  BOTTOM w0.305: C463.1 90.7,56.69 v2(91.03,57.02)
N30260943: length 1.9
  TOP w0.279: U32.40 v2(89.92,54.88)
  BOTTOM w0.305: C467.1 89.22,54.88 v2(89.92,54.88)
N30411655: length 3.8
  TOP w0.127: U22.7 v2(34.54,98.55)
  BOTTOM w0.127: TP18.1 v2(34.54,98.55) 35.43,98.55
N30424134: length 2.7
  TOP w0.305: U44.4 155.38,30.41 154.94,29.97 C225.1
N30424229: length 3.8
  TOP w0.127: C226.1 156.46,29.34 v2(155.83,29.97) 156.03,30.17 U44.5
  BOTTOM w0.127: v2(155.83,29.97) 155.7,30.1 R380.1
N30424257: length 2.5
  TOP w0.127: U44.10 157.33,38.46 v2(157.73,38.86)
  BOTTOM w0.127: v2(157.73,38.86) R362.1
N30488156: length 22.4
  TOP w0.254: L49.1 C240.1 ; D15.1 49.23,27.64 51.18,29.59 R145.1 R144.1 C217.2 53.09,32.38 L38.1 ; C209.2 43.05,28.45 44.32,27.18 D14.1
  TOP w0.508: D15.1 47.24,27.18 C240.1 D14.1
N30488160: length 2.4
  TOP w0.254: C209.1 C200.2 L33.2
N30488166: length 3.7
  TOP w0.254: C200.1 43.05,37.25 42.93,37.38 L28.2 C183.2
N30488172: length 7.1
  TOP w0.254: C183.1 L25.2 42.93,43.05 45.36,45.49 45.36,47.52 U34.2
N30488204: length 1.4
  TOP w0.254: L33.1 40.51,36.96 C199.1
N30488206: length 1.4
  TOP w0.254: L28.1 C182.1
N30488307: length 1.4
  TOP w0.254: L49.2 C216.2
N30488309: length 5.1
  TOP w0.254: C216.1 L42.2 L35.2 L31.1
N30488319: length 1.5
  TOP w0.254: L31.2 C184.2
N30488321: length 6.2
  TOP w0.254: U34.4 46.36,47.52 46.35,47.52 C175.1 L26.2 46.23,42.67 C184.1
N30488353: length 10.5
  TOP w0.254: C185.1 R131.1 52.32,42.16 50.42,44.07 49.02,44.07 47.36,45.73 47.36,47.52 U34.6
N30488365: length 1.9
  TOP w0.254: L35.1 C201.1
N30488367: length 1.9
  TOP w0.254: L42.1 C210.1
N30488419: length 12.4
  TOP w0.254: 54.86,35.69 L38.2 54.86,32.51 C217.1 ; 54.86,35.69 54.48,35.69 53.85,36.32 L32.1 ; 54.86,35.69 C202.1 ; C202.1 C192.2 R133.2 ; C202.1 57.32,35.69 57.57,35.43 D12.1
N30488423: length 7.6
  TOP w0.254: R131.2 C185.2 53.85,38.86 56.13,38.86 C192.1 R133.1
N30488512: length 1.4
  TOP w0.254: 56.77,33.27 C202.2
N30488558: length 12.5
  TOP w0.508: C244.1 49.53,25.15 v2(48.97,25.7) D15.2 ; R153.1 C243.1 v2(52.45,26.67) R145.2
  BOTTOM w0.508: v2(52.45,26.67) 51.49,25.7 v2(48.97,25.7)
N30489215: length 6.1
  TOP w0.508: C240.2 J16.1
N30489499: length 2.2
  TOP w0.127: C168.2 48.51,46.1 47.87,46.74 U34.7
N30491879: length 11.5
  TOP w0.127: v1(93.29,90.23) U27.AA12
  BOTTOM w0.127: C276.2 93.6,98.93 Y3.4 93.55,98.77 94.15,98.17 94.26,98.17 94.67,97.76 Y3.2 94.61,97.41 C292.2 94.61,92.71 93.98,92.07 93.98,91.57 93.29,90.88 v1(93.29,90.23)
N30491883: length 9.8
  TOP w0.102: U27.Y12 93.29,89.58 92.76,89.58 92.62,89.58 92.17,90.04 92.17,90.39 92.46,90.68 92.46,92.07 92.71,92.33
  TOP w0.127: v2(92.96,95.38) 92.71,95.12 92.71,92.33
  BOTTOM w0.127: v2(92.96,95.38) 93.6,96.01 C292.1 93.6,97.41 Y3.3
N30491911: length 11.2
  TOP w0.127: v2(95.38,96.39) 95.38,93.85 94.74,93.22 94.74,92.33 93.47,91.06 93.47,90.7 U27.AB12
  BOTTOM w0.127: v2(95.38,96.39) 95.5,96.52 95.5,98.55 95.17,98.88 Y3.1 94.67,100.15 C276.1
N30492439: length 6.1
  TOP w0.127: Y2.3 113.59,39.32 v2(113.66,39.24) 115.7,39.24 116.84,40.39 U40.5
  BOTTOM w0.127: C506.1 v2(113.66,39.24)
N30492465: length 3.6
  TOP w0.127: Y2.1 115.87,41.2 115.91,41.23 v2(115.95,41.23) 116.3,40.89 U40.4
  BOTTOM w0.127: C503.1 115.91,41.27 v2(115.95,41.23)
N30512853: length 2.4
  TOP w0.112: L44.1 118.94,30.16 119.46,29.64 119.46,29.03 C232.2
N30512862: length 2.4
  TOP w0.112: C233.2 119.81,29.03 119.81,29.64 120.33,30.16 L44.2
N30525930: length 17.1
  TOP w0.127: R183.2 v2(114.68,85.85) ; U27.P4 v1(99.14,85.68)
  LY3 w0.133: v2(114.68,85.85) 112.65,85.85 112.39,86.11 99.56,86.11 v1(99.14,85.68)
N30646408: length 3.9
  TOP w0.127: v2(157.1,38.86) 156.68,38.44 U44.11
  BOTTOM w0.127: v2(157.1,38.86) 157.1,37.46 R367.1
N30646808: length 3.6
  TOP w0.127: v2(154.18,38.86) 154.08,38.76 U44.15
  BOTTOM w0.127: R369.1 R364.2 154.31,38.73 v2(154.18,38.86)
N30646826: length 4.2
  TOP w0.305: v2(156.21,38.86) 155.83,38.86 155.38,38.41 U44.13
  BOTTOM w0.305: R368.1 R363.2 156.46,38.61 v2(156.21,38.86)
